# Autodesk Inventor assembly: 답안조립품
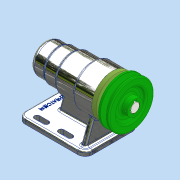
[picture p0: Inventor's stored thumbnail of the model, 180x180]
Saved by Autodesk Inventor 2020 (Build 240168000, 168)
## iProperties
Created: 2021-10
Part Number: 답안조립품
Document SubType Name: Assembly
Designer: user
Author: user
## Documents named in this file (12)
- C:\Users\user\Desktop\711007V1015\답안조립품.iam
- C:\Users\user\Desktop\711007V1015\V벨트풀리.ipt
- C:\Users\user\Desktop\711007V1015\멈춤나사 M3.ipt
- C:\Users\user\Desktop\711007V1015\베어링 6004.ipt
- C:\Users\user\Desktop\711007V1015\베어링 51202.ipt
- C:\Users\user\Desktop\711007V1015\본체.ipt
- C:\Users\user\Desktop\711007V1015\볼트 M4.ipt
- C:\Users\user\Desktop\711007V1015\어댑터슬리브.ipt
- C:\Users\user\Desktop\711007V1015\오일 실 20x35x7.ipt
- C:\Users\user\Desktop\711007V1015\축.ipt
- C:\Users\user\Desktop\711007V1015\커버.ipt
- C:\Users\user\Desktop\711007V1015\키 5x5.ipt
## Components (1 placed, 1 different names)
1. V벨트풀리:1
